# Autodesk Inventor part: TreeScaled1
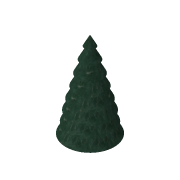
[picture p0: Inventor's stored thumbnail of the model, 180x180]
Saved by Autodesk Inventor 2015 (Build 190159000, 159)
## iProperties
Created: 2016-02
Part Number: TreeScaled1
Material: Generic
Document SubType Name: Modeling
Designer: Hafliði
Density: 1 g/cm^3
Appearance: Default
Author: Hafliði
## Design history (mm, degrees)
derived "tree.ipt"
feature "Solid1::tree.ipt" dims "d0" = 30
tag "TaggingFeature1"
body "Solid1"
